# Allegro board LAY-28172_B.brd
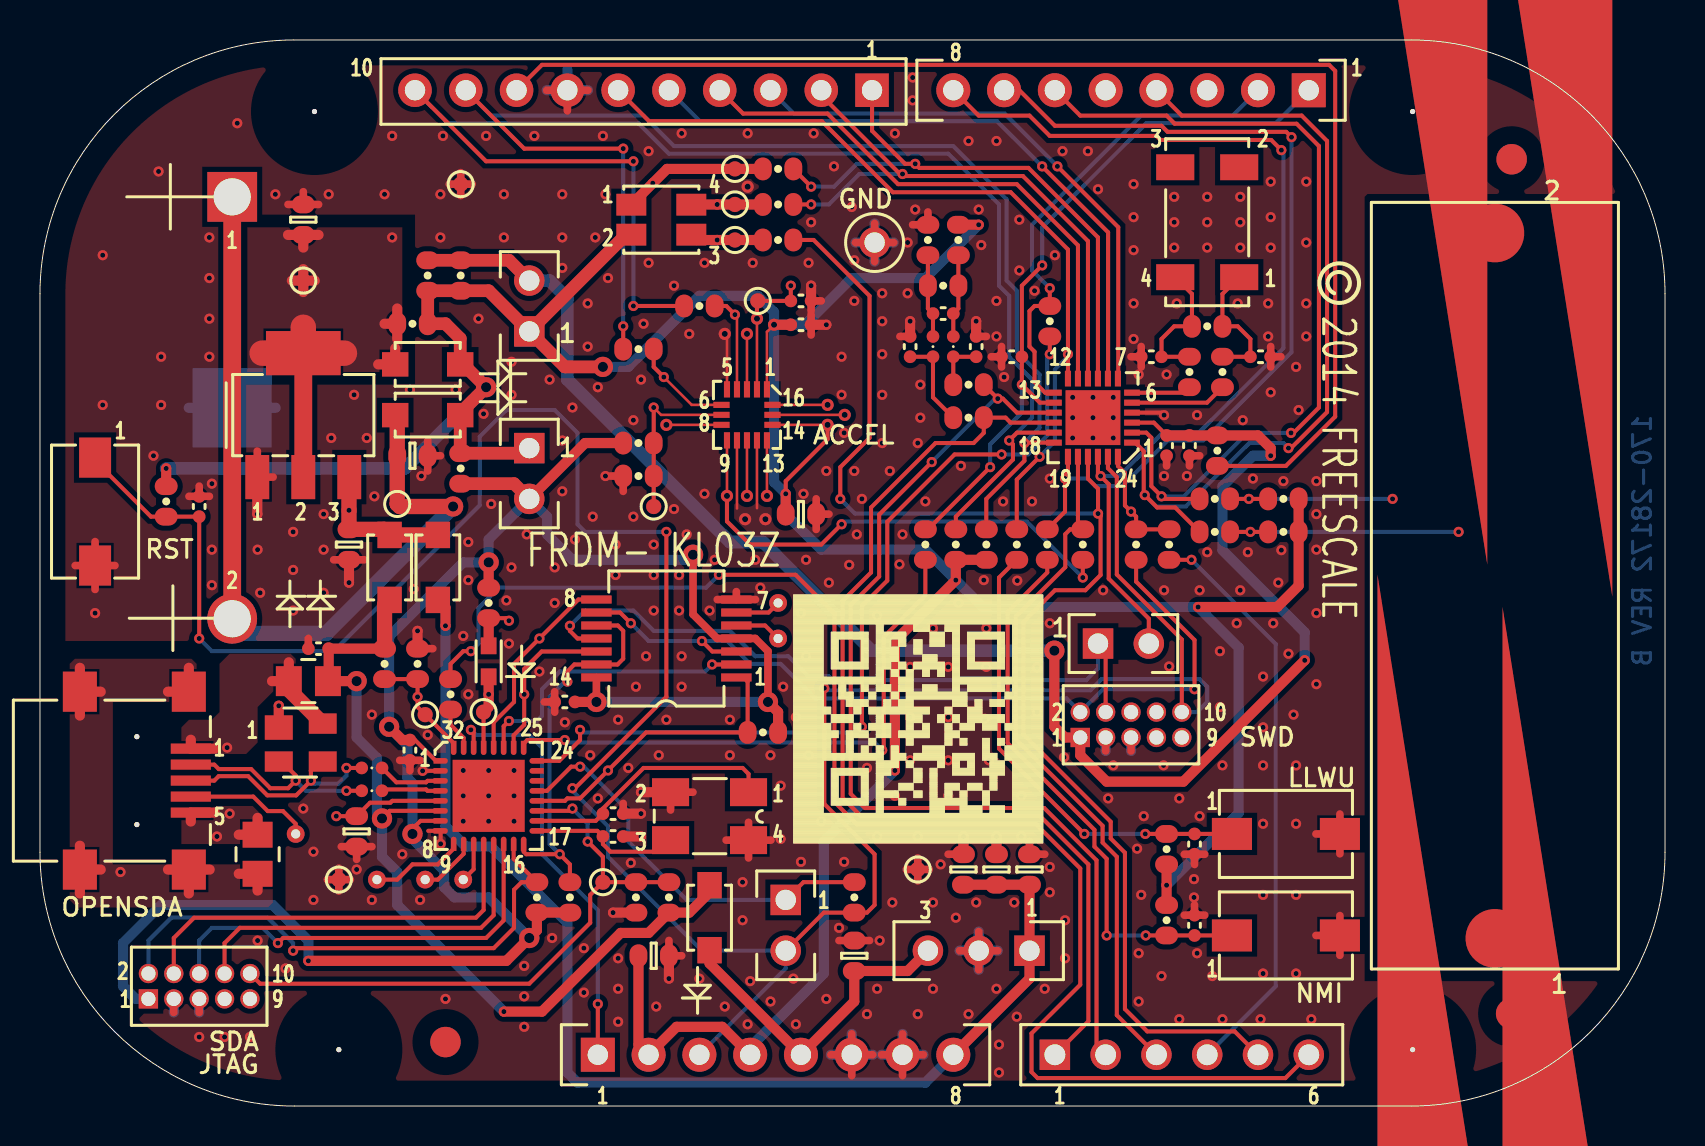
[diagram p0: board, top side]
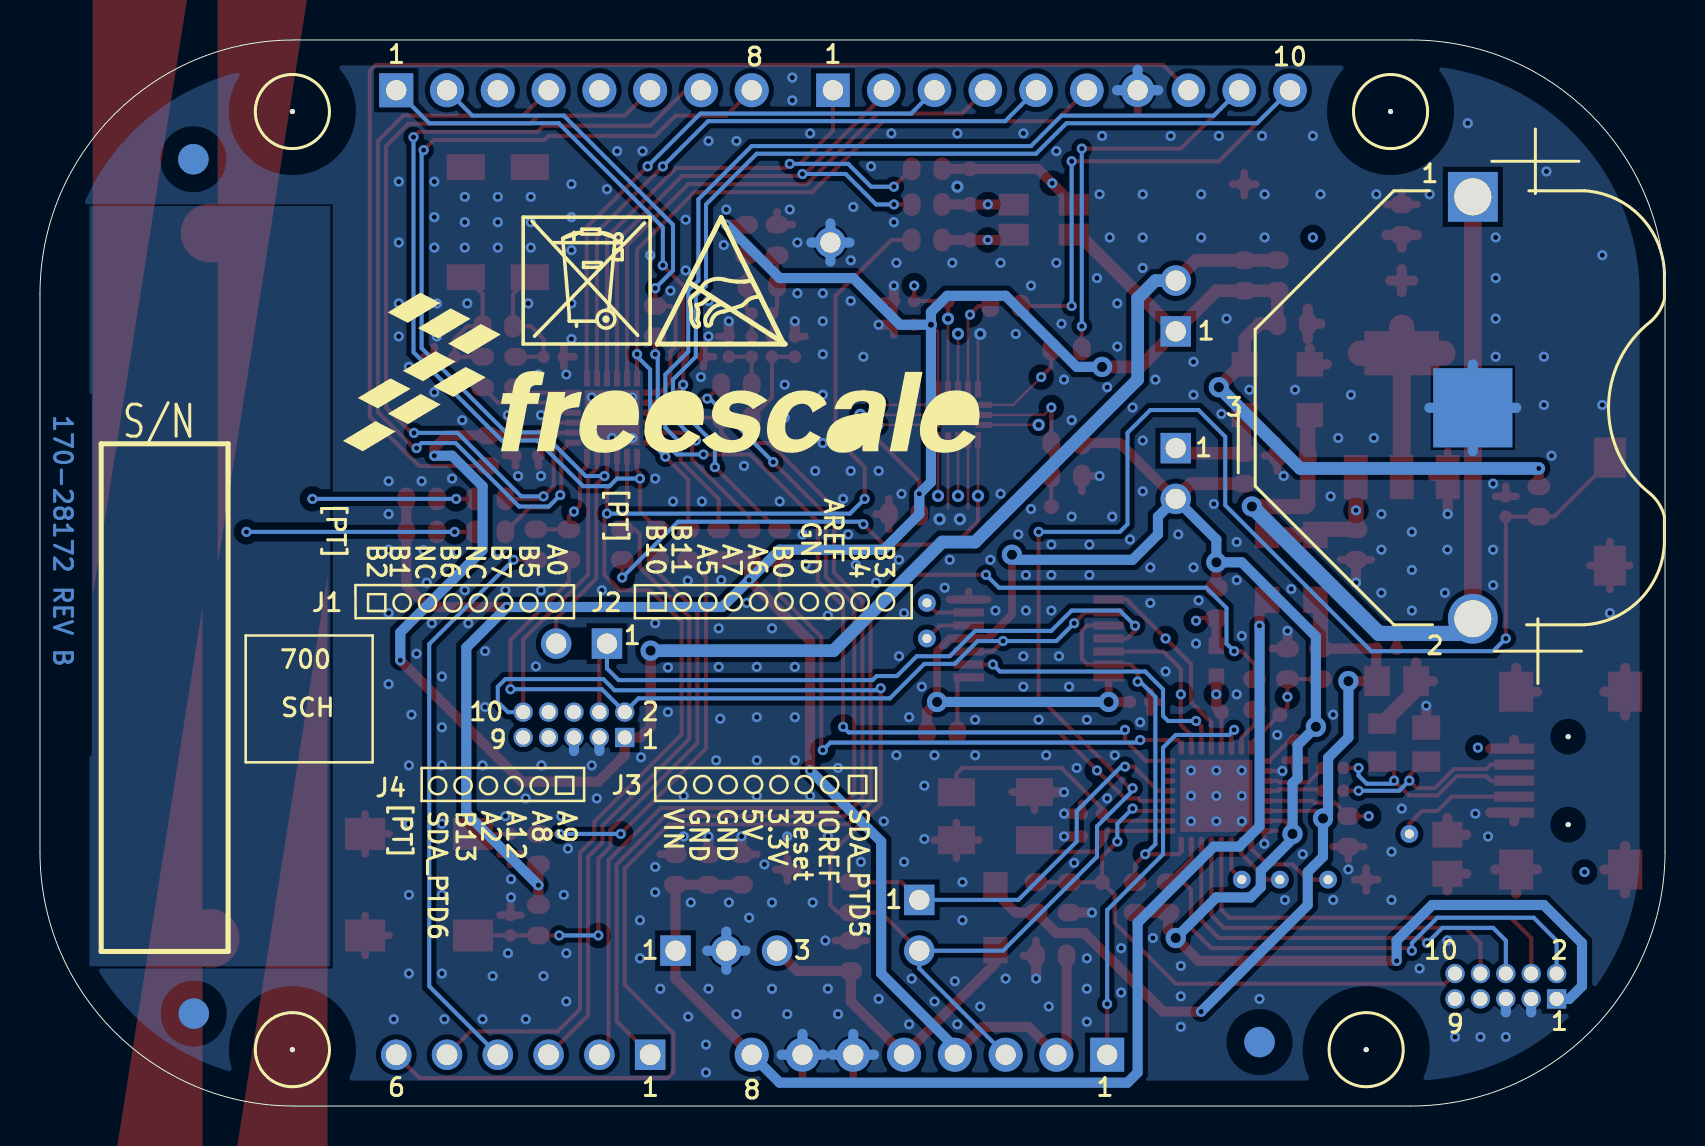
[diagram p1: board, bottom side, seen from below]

Outline 81.28 x 53.34 mm; copper layers: TOP, BOTTOM. Coordinates in mm from the lower left corner of the outline.
Outline path: 0,40.64 0,12.7 arc(3.74,3.72) 12.73,0 68.58,0 arc(77.56,3.72) 81.28,12.7 81.28,40.64 arc(77.56,49.62) 68.58,53.34 12.7,53.34 arc(3.72,49.62) 0,40.64

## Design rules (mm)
net group USB_SI_CONN_D: nets SDA_USB_CONN_DN SDA_USB_CONN_DP
net group USB_SI_D: nets SDA_USB_DN SDA_USB_DP
net group CLOCK: nets EXTAL SDA_EXTAL SDA_XTAL XTAL
net group POWER_SPACE: nets P3V3 P3V3_BATT P5V0_USBSER

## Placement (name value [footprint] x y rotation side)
BT1  3003  [BATT_21X20MM]  9.61 45.49 270 bottom
C1  0.1UF  [CC0402_25]  56.35 33.05 270 top
C2  12PF  [CC0402_25]  61.05 37.49 0 top
C7  12PF  [CC0402_25]  55.59 37.49 180 top
C8  1.0UF  [CC0402_25]  13.93 22.89 180 top
C9  1.0UF  [CC0402_25]  18.5 17.81 270 top
C10  22PF  [CC0402_25]  28.66 14.63 0 top
C11  22PF  [CC0402_25]  28.66 13.49 0 top
C12  2.2UF  [CC0603_OV]  15.84 13.74 270 top
C13  0.1UF  [CC0402_25]  7.96 30 90 top
C14  10uF  [CC0603_OV]  18.63 32.54 0 top
C15  10uF  [CC0603_OV]  15.46 28.09 270 top
C16  10uF  [CC0603_OV]  13.17 44.35 90 top
C17  0.1UF  [CC0402_25]  38.06 39.09 0 top
C18  10uF  [CC0603_OV]  38.06 29.62 0 top
C19  0.1UF  [CC0402_25]  38.06 40.28 0 top
C20  2.2UF  [CC0603_OV]  30.7 7.52 0 top
C22  1.0UF  [CC0402_25]  57.49 33.05 270 top
C26  10uF  [CC0603_OV]  49.49 11.84 90 top
C27  10uF  [CC0603_OV]  47.84 11.84 90 top
C28  10uF  [CC0603_OV]  46.19 11.84 90 top
C29  10uF  [CC0603_OV]  40.73 7.52 90 top
C30  0.1UF  [CC0402_25]  45.17 39.65 180 top
C31  2200PF  [CC0402_25]  43.52 38 90 top
C32  2200PF  [CC0402_25]  46.82 38 90 top
C33  0.1UF  [CC0402_25]  57.75 13.11 270 top
C34  0.1UF  [CC0402_25]  57.75 9.04 90 top
C35  0.1UF  [CC0402_25]  48.6 37.49 180 top
C36  0.1UF  [CC0402_25]  26.25 20.22 180 top
D1  LED GREEN  [LED_0603]  22.44 22.25 270 top
D2  MBR120VLSFT1G  [SOD-123]  17.49 26.95 90 top
D3  MBR120VLSFT1G  [SOD-123]  19.39 37.11 0 top
D4  CLV1A-FKB-CJ1M1F1BB7R4S3  [LED4_3P4X3MM_SMT]  31.08 44.35 90 top
D5  MBR120VLSFT1G  [SOD-123]  33.49 9.42 270 top
D6  TVLS14302AC0  [SOT_143]  13.04 18.19 270 top
D7  MBR120VLSFT1G  [SOD-123]  19.9 26.95 90 top
D8  MBR120VLSFT1G  [SOD-123]  19.39 34.57 0 top
E1  Slider_4  [ELECTRODE_TRI_4_12X38MM]  72.77 26.03 0 top
J1  CON_1X8  [CON_1X8_SKT_2P54_TH]  63.46 50.83 270 top
J2  CON_1X10  [HDR110]  41.62 50.83 270 top
J3  CON_1X8  [CON_1X8_SKT_2P54_TH]  27.9 2.57 90 top
J4  CON_1X6  [CON_SKT1X6_TH]  50.76 2.57 90 top
J5  HDR 1X2 TH  [HDR102]  24.47 32.92 0 top
J6  HDR 1X2 TH  [SH_HDR102_BOTTOM]  52.92 23.14 90 top
J7  HDR 2X5  [HDR_5X2_FTSH_TH_NSP]  52.03 18.44 90 top
J8  HDR 2X5  [HDR_5X2_FTSH_TH_NSP]  5.42 5.36 90 top
J9  USB MINI-B  [CON5_USB_B_UBB]  3.64 16.28 0 top
J10  HDR 1X2 TH  [HDR102]  24.47 38.76 180 top
J11  HDR 1X2 TH  [HDR102]  37.3 10.31 0 top
J22  HDR_1X3  [HDR103]  49.49 7.77 270 top
L3  330 OHM  [IND_0805]  13.42 21.26 0 top
L4  330 OHM  [IND_0805]  10.88 12.6 90 top
NOREF  -  []  12.7 53.34 0 top
NOREF#2  -  []  192.91 64.47 0 top
NOREF#3  -  []  52.42 36.4 0 top
NOREF#4  -  []  34.36 33.31 0 top
NOREF#5  -  []  37.68 13.11 0 top
NOREF#6  -  []  52.92 34.19 0 top
NOREF#7  -  []  34.36 33.31 0 top
NOREF#8  -  []  54.24 36.02 0 top
NOREF#9  -  []  -16.59 -36.7 0 top
NOREF#10  -  []  36.86 36.08 90 top
NOREF#11  -  []  81.28 12.7 90 top
NOREF#12  -  []  34.36 33.31 90 top
NOREF#13  -  []  51.42 36.4 0 top
NOREF#14  -  []  34.09 35.08 90 top
NOREF#15  -  []  33.86 36.08 0 top
NOREF#16  -  []  53.79 37.71 0 top
NOREF#17  -  []  12.88 1.39 0 top
NOREF#18  -  []  39.08 50.83 0 top
NOREF#19  -  []  65.11 41.05 270 top
NOREF#20  -  []  34.36 33.31 0 top
NOREF#21  -  []  13.74 2.72 0 top
NOREF#22  -  []  -381.97 185.27 0 top
NOREF#23  -  [unnamed#2]  20.28 3.2 0 top
NOREF#24  -  []  36.85 39.08 0 top
NOREF#25  -  []  50.59 32.37 90 top
NOREF#26  -  [unnamed#2]  73.61 47.37 0 top
NOREF#27  -  []  34.09 34.58 90 top
NOREF#28  -  []  52.92 34.19 90 top
NOREF#29  -  []  -32.92 -145.92 0 top
NOREF#30  -  []  70.32 0.01 90 top
NOREF#31  -  []  13.74 2.72 0 top
NOREF#32  -  []  54.62 34.19 90 top
NOREF#33  -  []  46.82 49.68 0 top
NOREF#34  -  []  0 41.47 0 top
NOREF#35  -  []  78.12 49.02 0 top
NOREF#36  -  []  54.72 32.37 0 top
NOREF#37  -  []  54.74 32.37 0 top
NOREF#38  -  [unnamed#2]  73.58 4.62 0 top
NOREF#39  -  []  34.09 34.08 0 top
NOREF#40  -  []  54.62 33.19 90 top
NOREF#41  -  []  -408 -339.88 0 top
NOREF#42  -  []  91.82 39.52 180 bottom
NOREF#43  -  []  54.66 12.88 180 bottom
NOREF#44  -  []  82.4 5.51 270 bottom
NOREF#45  -  [unnamed#2]  68.66 2.82 180 bottom
NOREF#46  -  [unnamed#2]  68.66 49.76 180 bottom
NOREF#47  -  [unnamed#2]  73.59 4.63 180 bottom
NOREF#48  -  []  50.38 38.13 180 bottom
NOREF#49  -  []  46.82 49.68 0 bottom
NOREF#50  -  [unnamed#2]  14.95 2.82 180 bottom
NOREF#51  -  []  54.61 5.51 180 bottom
NOREF#52  -  [unnamed#2]  20.28 3.2 180 bottom
NOREF#53  -  []  57.11 38.13 180 bottom
NOREF#54  -  [unnamed#2]  13.73 49.76 180 bottom
NOREF#55  -  [unnamed#2]  73.61 47.37 180 bottom
NOREF#56  -  []  66.13 33.17 180 bottom
R1  0  [RC0603_OV]  59.14 36.73 90 top
R2  10M  [RC0603_OV]  58.38 39.01 180 top
R3  0  [RC0603_OV]  57.49 36.73 90 top
R4  10K  [RC0603_OV]  26.5 10.44 90 top
R5  33  [RC0402_25]  16.6 15.77 0 top
R6  33  [RC0402_25]  16.6 16.92 0 top
R7  10K  [RC0603_OV]  36.16 18.69 0 top
R8  4.7K  [RC0603_OV]  31.46 10.44 90 top
R9  10K  [RC0603_OV]  29.81 10.44 270 top
R10  220  [RC0603_OV]  22.44 25.17 270 top
R11  0  [RC0603_OV]  20.54 20.6 90 top
R12  4.7K  [RC0603_OV]  17.23 22.12 270 top
R13  10K  [RC0603_OV]  6.31 30.25 270 top
R14  10K  [RC0603_OV]  18.88 22.12 90 top
R15  10K  [RC0603_OV]  24.85 10.44 90 top
R16  1K  [RC0603_OV]  50.51 39.27 90 top
R17  1K  [RC0603_OV]  44.28 28.09 90 top
R18  220  [RC0603_OV]  36.92 46.89 180 top
R19  220  [RC0603_OV]  36.92 45.11 0 top
R20  220  [RC0603_OV]  36.92 43.33 0 top
R21  4.7K  [RC0603_OV]  45.81 28.09 90 top
R22  4.7K  [RC0603_OV]  47.33 28.09 90 top
R23  10K  [RC0603_OV]  29.93 33.17 0 top
R24  10K  [RC0603_OV]  29.93 31.52 180 top
R25  0  [RC0603_OV]  58.89 32.79 270 top
R26  0  [RC0603_OV]  52.16 28.09 270 top
R27  0  [RC0603_OV]  19.39 41.55 90 top
R28  0  [RC0603_OV]  21.04 31.9 270 top
R29  510K  [RC0603_OV]  62.19 30.38 180 top
R30  510K  [RC0603_OV]  62.19 28.73 180 top
R31  0  [RC0603_OV]  40.73 10.44 270 top
R32  10  [RC0603_OV]  21.04 41.55 90 top
R33  0  [RC0603_OV]  54.83 28.09 270 top
R34  0  [RC0603_OV]  46.44 36.09 180 top
R35  0  [RC0603_OV]  46.44 34.44 180 top
R36  0  [RC0603_OV]  50.38 28.09 270 top
R37  0  [RC0603_OV]  48.86 28.09 270 top
R38  4.99K  [RC0603_OV]  45.94 43.33 270 top
R39  4.99K  [RC0603_OV]  44.41 43.33 90 top
R40  100  [RC0402_25]  44.67 38 90 top
R41  100  [RC0402_25]  45.68 38 90 top
R44  0  [RC0603_OV]  58.76 28.73 0 top
R45  0  [RC0603_OV]  58.76 30.38 0 top
R48  0  [RC0603_OV]  32.98 40.03 0 top
R49  0  [RC0603_OV]  29.93 37.87 0 top
R52  0  [RC0603_OV]  56.48 28.09 270 top
R53  0  [RC0603_OV]  18.63 39.14 0 top
R54  10K  [RC0603_OV]  56.35 12.85 90 top
R55  10K  [RC0603_OV]  56.35 9.3 270 top
RT1  10K  [RC0603_OV]  45.17 41.05 180 top
SW1  EVQ-PE105K  [SW2_SPST_3P5X6P0_5P0]  2.76 29.74 180 top
SW2  EVQ-PE105K  [SW2_SPST_3P5X6P0_5P0]  62.32 13.61 270 top
SW3  EVQ-PE105K  [SW2_SPST_3P5X6P0_5P0]  62.32 8.53 270 top
TP1  -  [TP_PTH]  21.17 11.33 0 top
TP2  -  [TP_PTH]  12.79 13.61 0 top
TP3  -  [TP_PTH]  19.27 11.33 0 top
TP4  -  [TP_PTH]  16.85 11.33 0 top
TP5  -  [TPAD_030]  28.16 11.2 0 top
TP6  -  [TPAD_030]  22.19 19.71 0 top
TP7  -  [TPAD_030]  19.27 19.58 0 top
TP11  -  [TP_PTH]  36.92 23.39 270 top
TP13  -  [TP_PTH]  36.92 25.17 270 top
TP15  -  [TPAD_030]  17.87 30.12 0 top
TP16  -  [TPAD_030]  13.17 41.3 0 top
TP17  -  [TPAD_030]  34.76 46.89 270 top
TP18  -  [TPAD_030]  34.76 45.11 270 top
TP19  -  [TPAD_030]  34.76 43.33 270 top
TP20  TEST POINT WHITE  [TEST_LOOP]  41.74 43.21 0 top
TP21  -  [TPAD_030]  14.95 11.33 0 top
TP22  -  [TPAD_030]  21.04 46.13 0 top
TP23  -  [TPAD_030]  43.9 11.84 0 top
TP24  -  [TPAD_030]  35.9 40.28 270 top
TP25  -  [TPAD_030]  30.7 30 270 top
U1  PKL03Z16VFK4  [QFN24_0P5_4X4MM]  52.67 34.44 90 top
U2  PK20DX128VFM5  [QFN32_S142EP]  22.44 15.52 0 top
U4  74LVC125ADB  [SSOP14]  31.33 23.39 180 top
U6  NCP1117ST33T3G  [SOT223]  13.17 34.57 0 top
U7  MMA8451Q  [QFN5X3_0P5_3X3]  35.36 34.58 270 top
Y1  32.768KHZ  [XTLOSC4_8X4MM]  58.38 44.22 90 top
Y2  8MHZ  [XTLOSC4_5X3MM_SM]  33.49 14.5 180 top

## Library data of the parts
BT1 = BATTERY_SKT_3V
C1 C2 C7-C20 C22 C26-C36 = CAP_NP
D1 = LED
D2 D3 D5 D7 D8 = DIODE_SCHTKY
D4 = CLV1A_LED_4P
D6 = DIODE_TVS_SOT143
E1 = ELECTRODE_TRI_2
J1 J3 = CONN_HDR_8X1
J2 = RCPT 1X10
J4 = CONN_HDR_6X1
J5 J6 J10 J11 = CONN_HDR_2X1
J7 J8 = CONN_HDR_5X2
J9 = USB_MINI_B_SKT
J22 = CONN_HDR_3X1
L3 L4 = BEAD
R1-R41 R44 R45 R48 R49 R52-R55 = RES
RT1 = THERMISTOR
SW1-SW3 = SW2P
TP1-TP7 TP11 TP13 TP15-TP25 = TESTLOOP
U1 = PKL03Z32_QFN_25P
U2 = PK20DX128V_QFN_32P
U4 = 74-125_14P
U6 = LD1117AS18
U7 = MMA8451Q_16P_A
Y1 = CRYSTAL1-4_SM
Y2 = CRYSTAL_JXS63

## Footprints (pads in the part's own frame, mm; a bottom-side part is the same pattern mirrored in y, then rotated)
BATT_21X20MM
  rect 2.489x2.489 hole 1.854: 1(0,0)
  round 2.489 hole 1.854: 2(21.11,0)
  rect 3.962x3.962 smd: 3(10.555,0)
CC0402_25
  round 0.635 smd: 1(-0.508,0) 2(0.508,0)
CC0603_OV
  oval 0.889x1.143 smd: 1(-0.762,0) 2(0.762,0)
CON5_USB_B_UBB
  round 0.254 hole 1.016 unplated: (1.2,2.2) (1.2,-2.2)
  rect 2.007x0.508 smd: 1(3.9,1.6) 2(3.9,0.8) 3(3.9,0) 4(3.9,-0.8) 5(3.9,-1.6)
  rect 1.702x2.007 smd: S1(3.8,4.45) S2(3.8,-4.45) S3(-1.65,4.45) S4(-1.65,-4.45)
CON_1X8_SKT_2P54_TH
  rect 1.702x1.702 hole 1.016: 1(0,0)
  round 1.702 hole 1.016: 2(0,-2.54) 3(0,-5.08) 4(0,-7.62) 5(0,-10.16) 6(0,-12.7) 7(0,-15.24) 8(0,-17.78)
CON_SKT1X6_TH
  rect 1.524x1.524 hole 1.041: 1(0,0)
  round 1.524 hole 1.041: 2(0,-2.54) 3(0,-5.08) 4(0,-7.62) 5(0,-10.16) 6(0,-12.7)
ELECTRODE_TRI_4_12X38MM
  custom 2.936x2.936 smd: 1(0,-17.645) 2(0,17.645)
HDR102
  rect 1.524x1.524 hole 1.016: 1(0,0)
  round 1.524 hole 1.016: 2(0,-2.54)
HDR103
  rect 1.524x1.524 hole 1.016: 1(0,0)
  round 1.524 hole 1.016: 2(0,-2.54) 3(0,-5.08)
HDR110
  rect 1.676x1.676 hole 1.016: 1(0,0)
  round 1.676 hole 1.016: 2(0,-2.54) 3(0,-5.08) 4(0,-7.62) 5(0,-10.16) 6(0,-12.7) 7(0,-15.24) 8(0,-17.78) 9(0,-20.32) 10(0,-22.86)
HDR_5X2_FTSH_TH_NSP
  rect 0.965x0.965 hole 0.711: 1(0,0)
  round 0.965 hole 0.711: 2(1.27,0) 3(0,-1.27) 4(1.27,-1.27) 5(0,-2.54) 6(1.27,-2.54) 7(0,-3.81) 8(1.27,-3.81) 9(0,-5.08) 10(1.27,-5.08)
IND_0805
  rect 1.295x1.499 smd: 1(-0.978,0) 2(0.978,0)
LED4_3P4X3MM_SMT
  rect 1.092x1.499 smd: 1(0.75,1.5) 2(-0.75,1.5) 3(-0.75,-1.5) 4(0.75,-1.5)
LED_0603
  rect 0.838x0.787 smd: A(-0.775,0) C(0.775,0)
QFN5X3_0P5_3X3
  rect 0.813x0.305 smd: 1(-1.275,1) 2(-1.275,0.5) 3(-1.275,0) 4(-1.275,-0.5) 5(-1.275,-1) 9(1.275,-1) 10(1.275,-0.5) 11(1.275,0) 12(1.275,0.5) 13(1.275,1)
  rect 0.305x0.813 smd: 6(-0.5,-1.275) 7(0,-1.275) 8(0.5,-1.275) 14(0.5,1.275) 15(0,1.275) 16(-0.5,1.275)
QFN24_0P5_4X4MM
  rect 0.305x0.787 smd: 1(-1.25,-1.953) 2(-0.75,-1.953) 3(-0.25,-1.953) 4(0.25,-1.953) 5(0.75,-1.953) 6(1.25,-1.953) 13(1.25,1.953) 14(0.75,1.953) 15(0.25,1.953) 16(-0.25,1.953) 17(-0.75,1.953) 18(-1.25,1.953)
  rect 0.787x0.305 smd: 7(1.953,-1.25) 8(1.953,-0.75) 9(1.953,-0.25) 10(1.953,0.25) 11(1.953,0.75) 12(1.953,1.25) 19(-1.953,1.25) 20(-1.953,0.75) 21(-1.953,0.25) 22(-1.953,-0.25) 23(-1.953,-0.75) 24(-1.953,-1.25)
  rect 2.743x2.743 smd: 25(0,0)
QFN32_S142EP
  custom 0.07x0.07 smd: 1(-2.4,1.751) 2(-2.4,1.251) 3(-2.4,0.751) 4(-2.4,0.25) 5(-2.4,-0.25) 6(-2.4,-0.751) 7(-2.4,-1.251) 8(-2.4,-1.751) 9(-1.751,-2.4) 10(-1.251,-2.4) 11(-0.751,-2.4) 12(-0.25,-2.4) 13(0.25,-2.4) 14(0.751,-2.4) 15(1.251,-2.4) 16(1.751,-2.4) 17(2.4,-1.751) 18(2.4,-1.251) 19(2.4,-0.751) 20(2.4,-0.25) 21(2.4,0.25) 22(2.4,0.751) 23(2.4,1.251) 24(2.4,1.751) 25(1.751,2.4) 26(1.251,2.4) 27(0.751,2.4) 28(0.25,2.4) 29(-0.25,2.4) 30(-0.751,2.4) 31(-1.251,2.4) 32(-1.751,2.4)
  rect 3.607x3.607 smd: 33(0,0)
RC0402_25
  round 0.635 smd: 1(-0.508,0) 2(0.508,0)
RC0603_OV
  oval 0.889x1.143 smd: 1(-0.762,0) 2(0.762,0)
SH_HDR102_BOTTOM
  rect 1.524x1.524 hole 1.016: 1(0,0)
  round 1.524 hole 1.016: 2(0,-2.54)
SOD-123
  rect 1.321x1.219 smd: A(-1.626,0) C(1.626,0)
SOT223
  rect 1.194x2.21 smd: 1(-2.3,-3.1) 2(0,-3.1) 3(2.3,-3.1)
  rect 3.734x2.21 smd: 4(0,3.1)
SOT_143
  rect 1.219x1.397 smd: 1(-0.75,-1.1)
  rect 1.016x1.397 smd: 2(0.95,-1.1) 3(0.95,1.1) 4(-0.95,1.1)
SSOP14
  rect 1.524x0.406 smd: 1(-3.5,1.95) 2(-3.5,1.3) 3(-3.5,0.65) 4(-3.5,0) 5(-3.5,-0.65) 6(-3.5,-1.3) 7(-3.5,-1.95) 8(3.5,-1.95) 9(3.5,-1.3) 10(3.5,-0.65) 11(3.5,0) 12(3.5,0.65) 13(3.5,1.3) 14(3.5,1.95)
SW2_SPST_3P5X6P0_5P0
  rect 1.6x2.007 smd: 1(0,-2.7) 2(0,2.7)
TEST_LOOP
  round 1.524 hole 1.016: 1(0,0)
TP_PTH
  round 0.889 hole 0.457: 1(0,0)
TPAD_030
  round 0.762 smd: 1(0,0)
unnamed#2
  round 1.524 smd: (0,0)
XTLOSC4_5X3MM_SM
  rect 1.854x1.397 smd: 1(-1.95,-1.2) 2(1.95,-1.2) 3(1.95,1.2) 4(-1.95,1.2)
XTLOSC4_8X4MM
  rect 1.295x1.905 smd: 1(-2.75,-1.6) 2(2.75,-1.6) 3(2.75,1.6) 4(-2.75,1.6)

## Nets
GND: BT1.3(NEG) C1.2 C2.2 C7.2 C8.2 C9.2 C10.2 C11.2 C12.2 C13.2 C14.2 C15.2 C16.2 C17.2 C18.2 C19.2 C20.2 C22.2 C26.2 C27.2 C28.2 C29.2 C31.2 C32.2 C33.2 C34.2 C35.2 C36.2 D6.1(GND) J2.7 J3.6 J3.7 J7.3(A2) J7.5(A3) J8.3(A2) J8.5(A3) J9.5(GND1) J22.2 L4.2 R9.2 R14.2 R24.2 R39.2 SW1.2(NO) SW2.2(NO) SW3.2(NO) TP20.1(PIN1) TP21.1(PIN1) TP22.1(PIN1) TP23.1(PIN1) U1.4(VREFL/VSS) U1.25(EXPAD) U2.2(VSS1) U2.8(VSSA) U2.33(EPAD) U4.7(GND) U6.1(GND) U7.5(GND1) U7.10(GND2) U7.12(GND3) Y2.2(GND1) Y2.4(GND2)
P3V3: C17.1 C18.1 C20.1 D3.C D4.2(COMMON_A) D8.C J3.2 J3.4 J5.1 J10.1 R13.1 R21.1 R22.1 R27.1 R28.1 R29.1 R30.1 R32.1 R38.1 R53.2 R54.1 R55.1 U7.1(VDDIO) U7.14(VDD)
P3V3_BATT: BT1.1(POS1) BT1.2(POS2) C14.1 D8.A TP15.1(PIN1)
P3V3_MCU: C1.1 C22.1 J7.1(A1) J10.2 R25.1 R27.2 R32.2 U1.3(VDD/VREFH)
P3V3_USBSER: C9.1 C36.1 J5.2 J8.1(A1) R4.1 R7.2 R10.1 R15.1 R23.1 R28.2 U2.1(VDD1) U2.7(VDDA) U4.4(O\E\2\) U4.14(VCC)
P3V3_VREG: C16.1 D3.A R53.1 TP16.1(PIN1) U6.2(VOUT) U6.4(TAB)
P5V0-9V0_VIN: C26.1 C27.1 C28.1 D7.A J3.8 J22.1
P5V0_SDA_USB_CONN_VBUS: D6.4(VDD) J9.1(VBUS) L3.1
P5V0_USBSER: C8.1 D2.A D5.A L3.2 R8.1 R12.1 U2.6(VREGIN)
P5V_USB_CONNECTORS: C29.1 D5.C J3.5 J22.3
A5: J4.6 R11.2
ACCEL_INT: R26.2 U7.9(INT2)
ACCEL_SCL: R48.2 U7.4(SCL)
ACCEL_SDA: R49.2 U7.6(SDA)
ADC0_SE0/CMP0_IN0/PTA12/IRQ_13/: J4.3 R26.1 U1.20(PTA12/IRQ_13/ADC0_SE0/CMP0_IN0/)
ADC0_SE1/CMP0_IN1/PTB5/IRQ_12/T: J1.7 R36.1 U1.19(PTB5/IRQ_12/ADC0_SE1/CMP0_IN1/T)
ADC0_SE2/PTA9/I2C0_SDA/SPI0_SCK: J4.1 R35.1 U1.16(PTA9/ADC0_SE2/I2C0_SDA/SPI0_SCK)
ADC0_SE3/PTA8/I2C0_SCL/SPI0_MOS: J4.2 R34.1 U1.15(PTA8/ADC0_SE3/I2C0_SCL/SPI0_MOS)
ADC0_SE5/CMP0_IN3/PTB1/IRQ_6/UA: J1.2 R16.2 U1.13(PTB1/IRQ_6/ADC0_SE5/CMP0_IN3/UA)
ADC0_SE6/PTB0/IRQ_5/LLWU_P4/EXT: J2.6 R37.1 U1.12(PTB0/IRQ_5/ADC0_SE6/EXTRG_IN/SP)
ADC0_SE12/CMP0_IN2/PTA0/IRQ_0/L: J1.8 J6.2 U1.22(PTA0/IRQ_0/ADC0_SE12/CMP0_IN2/T)
AREF: J2.8 R25.2
EXTAL: R1.1 U1.5(PTA3/EXTAL0/I2C0_SCL/I2C0_SDA/U)
LEDRGB_BLUE: D4.3(BLUE_C) R20.1 TP19.1(PIN1)
LEDRGB_GREEN: D4.4(GREEN_C) R19.1 TP18.1(PIN1)
LEDRGB_RED: D4.1(RED_C) R18.2 TP17.1(PIN1)
MMA8451_BYP: C19.1 TP24.1(PIN1) U7.2(BYP)
PTA2/CMP0_OUT/SWD_DIO: J4.4 R52.2
PTA5/RTC_CLKIN/TPM0_CH1/SPI0_SS: J2.3 U1.7(PTA5/RTC_CLK_IN/TPM0_CH1/S\P\I\)
PTA6/TPM0_CH0/SPI0_MISO: J2.5 U1.8(PTA6/TPM0_CH0/SPI0_MISO)
PTA7/IRQ_4/SPI0_MISO/SPI0_MOSI: J2.4 U1.11(PTA7/IRQ_4/SPI0_MISO/SPI0_MOSI)
PTB3/IRQ_10/I2C0_SCL/UART0_TX: J2.10 R21.2 R48.1 U1.17(PTB3/IRQ_10/I2C0_SCL/UART0_TX)
PTB4/IRQ_11/I2C0_SDA/UART0_RX: J2.9 R22.2 R49.1 U1.18(PTB4/IRQ_11/I2C0_SDA/UART0_RX)
PTB6/IRQ_2/LPTMR0_ALT3/TPM1_CH1: J1.4 R44.1 U1.1(PTB6/IRQ_2/TPM1_CH1/TPM_CLKIN1/)
PTB7/IRQ_3/TPM1_CH0: J1.6 R45.1 U1.2(PTB7/IRQ_3/TPM1_CH0)
PTB10/TPM0_CH1/SPI0_SS_B: J2.1 R18.1 U1.9(PTB10/TPM0_CH1/S\P\I\0\_\S\S\)
PTB11/TPM0_CH0/SPI0_MISO: J2.2 R19.2 U1.10(PTB11/TPM0_CH0/SPI0_MISO)
PTB13/CLKOUT32K/TPM1_CH1/RTC_CL: J4.5 R20.2 U1.21(PTB13/CLKOUT32K/TPM1_CH1/RTC_CL)
RST_TGTMCU: C13.1 J3.3 J7.10(B5) J11.2 R13.2 R31.2 SW1.1(COMMON) U1.23(PTA1/IRQ_1/TPM_CLKIN0/R\E\S\E\T)
SDA_EXTAL: C11.1 U2.17(EXTAL0/PTA18/FTM0_FLT2/FTM_CLKI) Y2.3
SDA_JTAG_TCLK: J8.4(B2) U2.12(JTAG_TCLK/SWD_CLK/EZP_CLK/TSI0_)
SDA_JTAG_TDI: J8.8(B4) U2.13(JTAG_TDI/EZP_DI/TSI0_CH2/PTA1/U)
SDA_JTAG_TDO: J8.6(B3) U2.14(JTAG_TDO/TRACE_SWO/EZP_DO/TSI0_)
SDA_JTAG_TMS: J8.2(B1) R15.2 U2.15(JTAG_TMS/SWD_DIO/TSI0_CH4/PTA3/)
SDA_LED: D1.C(CATHODE) TP6.1(PIN1) U2.29(PTD4/SPI0_PCS1/U\A\R\T\0\_\R\T\)
SDA_LED_R: D1.A(ANODE) R10.2
SDA_PTD5: J3.1 U2.30(ADC0_SE6B/PTD5/SPI0_PCS2/U\A\R\)
SDA_PTD6: R11.1 U2.31(ADC0_SE7B/PTD6/SPI0_PCS3/UART0_)
SDA_RST: J8.10(B5) R8.2 R9.1 TP5.1(PIN1) U2.19(R\E\S\E\T\)
SDA_RST_TGTMCU: J11.1 R31.1 U2.21(ADC0_SE9/TSI0_CH6/PTB1/I2C0_SDA)
SDA_SPI0_SCK: U2.26(PTC5/SPI0_SCK/LPTMR0_ALT2/I2S0_) U4.12(4A)
SDA_SPI0_SIN: U2.28(CMP0_IN1/PTC7/SPI0_SIN/USB_SOF_) U4.8(3Y)
SDA_SPI0_SOUT: U2.27(CMP0_IN0/PTC6/SPI0_SOUT/PDB0_EX) U4.2(1A)
SDA_SWD_EN: R4.2 U2.16(N\M\I\/E\Z\P\_\C\S\/TSI0_CH5/PT) U4.10(O\E\3\) U4.13(O\E\4\)
SDA_SWD_OE_B: R7.1 U2.20(ADC0_SE8/TSI0_CH0/PTB0/I2C0_SCL) U4.1(O\E\1\)
SDA_USB_CONN_DN: D6.2(I/O1) J9.2(D-) R5.1
SDA_USB_CONN_DP: D6.3(I/O2) J9.3(D+) R6.1
SDA_USB_DN: R5.2 U2.4(USB0_DM)
SDA_USB_DP: R6.2 U2.3(USB0_DP)
SDA_USB_P5V_SENSE: R12.2 R14.1 TP7.1(PIN1) U2.32(PTD7/CMT_IRO/UART0_TX/FTM0_CH7/)
SDA_USB_VOUT33: C12.1 U2.5(VOUT33)
SDA_USBSHIELD: J9.S1(SHLD1) J9.S2(SHLD2) J9.S3(SHLD3) J9.S4(SHLD4) L4.1
SDA_XTAL: C10.1 U2.18(XTAL0/PTA19/FTM1_FLT0/FTM_CLKIN) Y2.1
SW_LLWU: C33.1 R37.2 R54.2 SW2.1(COMMON)
SW_NMI_B: C34.1 R36.2 R55.2 SW3.1(COMMON)
SWD_CLK_TGTMCU: J6.1 J7.4(B2) U4.11(4Y)
SWD_DIO_TGTMCU: J7.2(B1) R33.2 U4.3(1Y) U4.9(3A)
TC_74125_SPARE_I_TP: TP11.1(PIN1) U4.5(2A)
TC_74125_SPARE_O_TP: TP13.1(PIN1) U4.6(2Y)
TC_EXTAL_TP: TP3.1(PIN1) U2.10(EXTAL32)
TC_SDA_USB_ID_TP: J9.4(ID) TP2.1(PIN1)
TC_VBAT_TP: TP1.1(PIN1) U2.11(VBAT)
TC_XTAL_TP: TP4.1(PIN1) U2.9(XTAL32)
THER_A: C32.1 R34.2 R41.1
THER_B: C31.1 R35.2 R40.1
THER_N: C30.2 R39.1 R40.2 RT1.2
THER_P: C30.1 R38.2 R41.2 RT1.1
TOUCH_A: E1.1 R29.2 R45.2
TOUCH_B: E1.2 R30.2 R44.2
UART0_RX_TGTMCU: R17.1 U2.25(PTC4/SPI0_PCS0/UART1_TX/FTM0_CH)
UART0_TX_TGTMCU: R16.1 U2.24(CMP1_IN1/PTC3/SPI0_PCS1/UART1_R)
VREF_CAP/CMP_IN5/PTB2/IRQ_7/UAR: C35.1 J1.1 R17.2 U1.14(PTB2/IRQ_7/VREF_CAP/CMP_IN5/UAR)
XTAL: R3.1 U1.6(PTA4/XTAL0/I2C0_SDA/I2C0_SCL/UA)
N20057318: C15.1 D2.C D7.C U6.3(VIN)
N20181399: R23.2 R24.1 TP25.1(PIN1) U7.7(SA0)
N51885583: C2.1 R1.2 R2.1 Y1.1
N51886520: R33.1 R52.1 U1.24(PTA2/CMP0_OUT/SWD_DIO)
N51910298: C7.1 R2.2 R3.2 Y1.4

Pads without a net: J1 3 5; J7 6 7 8 9; J8 7 9; U2 22 23; U7 3 8 11 13 15 16; Y1 2 3

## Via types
v1: diameter 0.508, hole 0.254, TOP to BOTTOM, 490 vias
v2: diameter 0.61, hole 0.305, TOP to BOTTOM, 14 vias
v3: diameter 1.016, hole 0.508, TOP to BOTTOM, 13 vias

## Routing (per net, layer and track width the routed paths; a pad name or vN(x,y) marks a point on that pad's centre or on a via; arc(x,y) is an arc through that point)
GND: length 147.3
  TOP w0.127: 34.86,29.9 U7.10 ; 35.86,29.91 U7.12 ; v2(34.25,38.63) 34.36,38.52 U7.5
  TOP w0.203: U1.4 56.1,34.69 v1(56.22,34.57) ; v1(20.04,13.12) U2.8 19.42,13.77 ; U2.2 v1(19.14,16.77)
  TOP w0.381: 12.4,45.11 C16.2 ; C16.2 13.93,45.11 ; C16.2 13.17,45.75 ; 48.09,36.98 C35.2 ; C35.2 47.58,37.49 ; C35.2 48.09,38 ; C13.2 7.96,31.02 ; C13.2 7.45,30.51 ; C13.2 8.47,30.51 ; SW3.2 65.02,9.53 ; SW3.2 65.02,7.54 ; SW3.2 63.82,8.53 ; 1.76,27.04 SW1.2 ; SW1.2 3.75,27.04 ; SW1.2 2.76,28.24 ; SW1.2 2.76,25.85 ; C2.2 61.56,38 ; C2.2 61.56,36.98 ; C2.2 62.07,37.49 ; 20.47,46.13 TP22.1 ; TP22.1 21.04,46.7 ; TP22.1 21.04,45.55 ; TP22.1 21.62,46.13 ; C8.2 13.42,23.4 ; 26.38,49.79 J2.7 ; J2.7 25.35,50.83 ; J2.7 27.41,50.83 ; C10.2 29.17,15.14 ; 7.96,4.68 J8.5 ; 10.87,32.77 U6.1 11.66,31.47 ; 50.26,12.6 C26.2 49.49,13.24 ; 43.14,1.52 J3.7 ; J3.7 44.19,2.57 ; J3.7 42.1,2.57 ; J3.7 43.14,3.61 ; 18.5,16.79 C9.2 ; C9.2 17.99,17.3 ; C9.2 19.01,17.3 ; R14.2 19.65,22.89 ; 25.23,20.22 C36.2 ; C36.2 25.74,19.71 ; C36.2 25.74,20.73 ; 57.24,12.6 C33.2 ; C33.2 58.26,12.6 ; C33.2 57.75,12.09 ; C7.2 55.08,38 ; C7.2 54.57,37.49 ; C7.2 55.08,36.98 ; 46.95,6.82 J22.2 ; J22.2 47.91,7.77 ; J22.2 46,7.77 ; J22.2 46.95,8.73 ; 14.37,11.33 TP21.1 ; TP21.1 14.95,10.75 ; TP21.1 15.52,11.33 ; TP21.1 14.95,11.9 ; C34.2 58.26,9.55 ; C34.2 57.24,9.55 ; C34.2 57.75,10.06 ; 33.88,25.34 U4.7 ; U4.7 35.79,25.34 ; U4.7 34.83,25.74 ; TP23.1 44.48,11.84 ; TP23.1 43.9,11.26 ; TP23.1 43.33,11.84 ; TP23.1 43.9,12.41 ; 54.57,17.76 J7.5 ; 57.49,32.03 C22.2 58,32.54 ; 38.57,39.6 C17.2 38.57,38.58 ; Y2.4 36.56,13.3 ; Y2.4 35.44,12.41 ; Y2.4 34.32,13.3 ; Y2.4 35.44,14.2 ; 41.49,8.28 C29.2 39.96,8.28 ; 45.42,12.6 C28.2 ; 14.69,27.33 C15.2 16.22,27.33 ; 15.84,12.34 C12.2 ; C12.2 15.07,12.98 ; C12.2 16.6,12.98 ; 63.82,13.61 SW2.2 ; SW2.2 65.02,14.61 ; SW2.2 65.02,12.62 ; 43.65,44.09 R39.2 44.41,44.73 ; TP20.1 42.7,43.21 ; TP20.1 40.79,43.21 ; TP20.1 41.74,44.16 ; TP20.1 41.74,42.25 ; J3.6 40.6,3.61 ; J3.6 40.6,1.52 ; J3.6 39.56,2.57 ; J3.6 41.65,2.57 ; 39.08,40.28 C19.2 38.57,39.77 ; 43.01,38.51 C31.2 ; 32.66,15.7 Y2.2 31.54,14.81 ; 31.46,8.28 C20.2 32.1,7.52 ; C14.2 19.39,33.3 ; C14.2 20.03,32.54 ; C14.2 19.39,31.77 ; C18.2 39.46,29.62 ; C18.2 38.82,30.38 ; C18.2 38.82,28.85 ; 56.35,32.03 C1.2 ; 28.53,31.52 R24.2 29.17,30.76 ; C32.2 47.34,38.51 ; 53.3,17.76 J7.3 ; 6.69,4.68 J8.3
  TOP w0.508: v1(47.84,13.49) C27.2 ; C11.2 v1(30.06,13.49) ; 8.74,14.68 J9.5 7.54,14.24 ; 9.94,13.58 L4.2 10.88,14.42 ; C32.2 v1(46.82,39.27) ; v1(46.19,13.49) C28.2 ; v1(38.57,41.05) C19.2 ; C10.2 v1(30.06,14.63) ; C20.2 v1(31.46,6.38) ; C31.2 v1(43.52,39.27) ; v1(30.06,15.7) Y2.2 ; R14.2 v1(18.88,23.77) ; C15.2 v1(15.46,26.19) ; D6.1 v1(11.94,20.03) ; C17.2 v1(39.33,39.09) ; R9.2 v1(28.66,9.68) ; U6.1 v1(10.87,29.62)
  BOTTOM w0.508: 39.56,2.57 J3.6 ; J3.6 41.65,2.57 ; J3.6 40.6,3.61 ; 7.44,34.94 BT1.3 ; BT1.3 9.61,32.76 ; BT1.3 11.79,34.94 ; BT1.3 9.61,37.11 ; 7.96,4.68 J8.5 ; TP20.1 41.74,44.16 ; TP20.1 40.79,43.21 ; TP20.1 41.74,42.25 ; TP20.1 42.7,43.21 ; J22.2 46.95,8.73 ; J22.2 47.91,7.77 ; J22.2 46.95,6.82 ; J22.2 46,7.77 ; 6.69,4.68 J8.3 ; J3.7 44.19,2.57 ; J3.7 43.14,3.61 ; J3.7 42.1,2.57 ; J2.7 26.38,51.86 ; J2.7 27.41,50.83 ; J2.7 25.35,50.83 ; 53.3,17.76 J7.3 ; 54.57,17.76 J7.5
  vias: v1(2.76,24.66) v1(3.14,42.57) v1(3.14,35.08) v1(5.68,32.54) v1(5.93,46.76) v1(6.06,37.49) v1(6.06,35.08) v1(7.96,3.45) v1(8.47,43.46) v1(8.47,41.43) v1(8.47,39.4) v1(8.47,37.49) v1(8.6,31.14) v1(8.6,27.84) v1(8.6,26.06) v1(8.85,13.49) v1(9.23,3.45) v1(9.49,14.63) v1(9.87,49.17) v1(10.5,3.45) v1(10.88,27.84) v1(10.88,8.28) v1(11.01,25.68) v1(11.77,45.62) v1(12.28,6.88) v1(12.66,28.73) v1(12.66,26.82) v1(12.66,24.79) v1(13.17,14.88) v1(13.68,12.73) v1(13.68,10.31) v1(14.19,29.62) v1(14.19,27.84) v1(14.19,25.68) v1(14.44,45.62) v1(14.57,33.43) v1(15.71,35.59) v1(15.84,11.84) v1(16.34,33.43) v1(16.6,19.58) v1(16.6,10.31) v1(16.73,30.51) v1(17.23,45.62) v1(17.61,48.54) v1(18.12,12.6) v1(18.5,35.84) v1(18.69,25.87) v1(19.08,31.52) v1(19.01,10.31) v1(19.39,18.57) v1(20.03,45.62) v1(20.03,43.46) v1(20.15,48.54) v1(20.28,5.36) v1(20.79,35.84) v1(21.17,23.52) v1(21.17,16.79) v1(21.17,15.52) v1(21.17,14.25) v1(21.42,28.22) v1(21.42,26.31) v1(21.42,20.6) v1(21.93,39.4) v1(22.19,34.63) v1(22.31,48.54) v1(22.44,16.79) v1(22.44,15.52) v1(22.44,14.25) v1(22.57,30.12) v1(23.2,45.62) v1(23.2,43.46) v1(23.33,25.3) v1(23.46,23.14) v1(23.58,37.24) v1(23.58,35.59) v1(23.58,26.95) v1(23.71,16.79) v1(23.71,15.52) v1(23.71,14.25) v1(24.22,7.01) v1(24.22,5.49) v1(24.22,3.96) v1(24.35,28.6) v1(24.73,48.54) v1(24.98,21.74) v1(25.49,36.35) v1(25.62,8.41) v1(25.74,26.95) v1(25.74,25.17) v1(26.12,45.62) v1(26.12,43.46) v1(26.12,41.94) v1(26.12,33.3) v1(26.12,30.76) v1(26.25,19.2) v1(26.63,34.95) v1(26.76,28.35) v1(27.2,7.9) v1(27.2,5.68) v1(27.39,40.16) v1(27.39,38) v1(27.52,17.55) v1(27.65,29.49) v1(27.77,43.46) v1(27.9,35.97) v1(27.9,15.39) v1(28.16,48.54) v1(28.28,45.62) v1(28.28,31.52) v1(28.41,41.43) v1(28.79,28.09) v1(28.79,26.57) v1(28.92,19.33) v1(28.92,7.39) v1(28.92,5.87) v1(28.92,4.22) v1(29.43,16.92) v1(29.55,12.17) v1(29.68,34.32) v1(29.68,29.49) v1(29.81,20.98) v1(30.06,36.35) v1(30.19,39.14) v1(30.31,22.5) v1(30.44,47.78) v1(30.44,42.19) v1(30.7,28.09) v1(30.7,26.57) v1(30.7,24.79) v1(30.82,4.98) v1(30.95,17.55) v1(31.33,19.33) v1(31.71,41.05) v1(31.71,29.87) v1(31.97,26.57) v1(31.97,24.79) v1(32.09,48.67) v1(32.09,22.5) v1(32.09,20.98) v1(32.35,28.6) v1(32.47,38.63) v1(32.98,6.38) v1(33.24,42.19) v1(33.24,30.63) v1(33.49,24.79) v1(33.74,27.33) v1(34.25,4.98) v1(34.51,19.33) v1(34.51,17.55) v1(35.14,11.2) v1(35.14,9.3) v1(35.39,48.67) v1(35.39,4.09) v1(35.52,6.25) v1(35.65,42.19) v1(35.78,27.33) v1(36.03,25.93) v1(36.54,17.55) v1(36.54,5.23) v1(37.05,16.03) v1(37.05,13.36) v1(37.17,20.98) v1(37.68,6.38) v1(37.81,19.46) v1(37.81,4.09) v1(38.06,24.66) v1(38.06,12.22) v1(38.19,30.63) v1(38.32,27.33) v1(38.32,22.5) v1(38.44,42.19) v1(38.44,17.55) v1(38.57,44.22) v1(38.7,48.67) v1(39.08,14.25) v1(39.33,31.78) v1(39.33,5.36) v1(39.46,26.19) v1(39.71,47.02) v1(39.97,8.92) v1(40.09,37.49) v1(40.09,35.59) v1(40.22,33.68) v1(40.22,12.22) v1(40.47,27.08) v1(40.6,44.98) v1(40.73,42.32) v1(40.73,40.28) v1(40.73,31.78) v1(40.86,28.6) v1(41.11,30.38) v1(41.36,16.92) v1(41.36,4.6) v1(41.87,24.54) v1(41.87,13.49) v1(41.87,5.87) v1(42,8.28) v1(42.13,40.67) v1(42.13,39.27) v1(42.13,37.62) v1(42.13,35.59) v1(42.13,33.17) v1(42.51,31.78) v1(42.63,10.19) v1(42.76,48.67) v1(42.76,15.52) v1(42.99,27.1) v1(43.14,28.6) v1(43.4,43.21) v1(43.4,40.67) v1(43.52,21.97) v1(43.52,19.46) v1(43.52,17.3) v1(43.65,51.46) v1(43.65,50.32) v1(43.78,44.86) v1(43.9,33.17) v1(43.9,13.49) v1(43.9,4.6) v1(44.03,36.09) v1(44.03,34.44) v1(44.28,30.25) v1(44.67,23.9) v1(44.67,10.19) v1(44.67,5.87) v1(45.05,12.09) v1(45.43,21.97) v1(45.43,19.46) v1(45.43,17.3) v1(45.43,15.52) v1(45.81,9.42) v1(45.94,25.17) v1(46.06,32.03) v1(46.44,48.29) v1(46.44,4.6) v1(46.82,10.19) v1(46.95,44.86) v1(47.08,43.08) v1(47.21,26.31) v1(47.26,19.38) v1(47.33,23.9) v1(47.33,21.97) v1(47.46,17.3) v1(47.84,48.29) v1(47.84,40.28) v1(47.84,38.51) v1(47.84,5.87) v1(47.97,3.07) v1(47.97,1.68) v1(48.17,30.25) v1(48.22,36.47) v1(48.73,10.19) v1(48.88,26.29) v1(48.86,4.47) v1(48.98,44.35) v1(48.98,41.81) v1(49.09,15.52) v1(49.09,13.49) v1(49.62,30.25) v1(49.75,40.79) v1(49.87,21.95) v1(49.87,19.71) v1(50.25,5.87) v1(50.51,31.39) v1(50.51,24.16) v1(50.51,11.96) v1(50.51,10.69) v1(50.76,42.57) v1(51.14,47.78) v1(51.22,17.45) v1(51.27,9.3) v1(51.27,7.39) v1(51.65,35.46) v1(51.65,34.44) v1(51.65,33.43) v1(52.41,47.78) v1(52.67,35.46) v1(52.67,34.44) v1(52.67,33.43) v1(52.92,45.87) v1(53.17,25.81) v1(53.43,15.39) v1(53.68,35.46) v1(53.68,34.44) v1(53.68,33.43) v1(53.68,17.04) v1(54.7,46.13) v1(54.7,44.48) v1(54.7,42.82) v1(54.7,40.16) v1(54.7,38.38) v1(54.88,12.88) v1(54.95,36.6) v1(54.95,7.65) v1(54.95,5.23) v1(55.08,10.57) v1(55.21,14.5) v1(56.1,6.5) v1(56.2,17.04) v1(56.22,31.52) v1(56.22,25.81) v1(56.35,36.6) v1(56.48,22) v1(56.73,45.49) v1(56.73,44.22) v1(56.73,42.95) v1(56.86,40.16) v1(56.98,15.39) v1(56.98,4.34) v1(57.37,31.52) v1(57.72,11.35) v1(57.72,10.44) v1(57.87,34.57) v1(57.87,7.65) v1(58,25.81) v1(58,14.5) v1(58.38,45.49) v1(58.38,44.22) v1(58.38,42.95) v1(58.38,27.71) v1(58.64,6.5) v1(59.02,22.76) v1(59.02,19.96) v1(59.14,17.04) v1(59.14,4.34) v1(59.86,24.16) v1(59.91,40.16) v1(60.03,45.49) v1(60.03,44.22) v1(60.03,42.95) v1(60.03,25.81) v1(60.16,34.32) v1(60.41,27.71) v1(60.67,31.39) v1(61.05,4.34) v1(61.18,21.49) v1(61.18,18.95) v1(61.18,17.04) v1(61.18,14.12) v1(61.18,10.57) v1(61.18,6.63) v1(61.43,40.16) v1(61.43,38.51) v1(61.56,46.25) v1(61.56,44.48) v1(61.56,42.95) v1(61.56,35.71) v1(61.68,24.16) v1(61.94,26.19) v1(62.09,27.81) v1(62.19,31.27) v1(62.45,22.63) v1(62.7,19.58) v1(62.83,36.98) v1(62.83,17.04) v1(62.83,14.12) v1(62.83,10.57) v1(62.83,6.63) v1(62.95,34.82) v1(63.33,46.25) v1(63.33,43.21) v1(63.33,40.16) v1(63.33,38.51) v1(63.59,4.34) v1(63.84,31.27) v1(63.84,29.62) v1(63.84,27.84) v1(63.84,24.66) v1(63.84,21.11) v2(35.27,29.36) v2(35.39,46) v2(36.28,29.36)
P3V3: length 189
  TOP w0.127: U7.14 v2(39.39,34.08) ; U7.1 36.36,38.74 v2(36.72,39.09)
  TOP w0.203: v1(37.3,30.63) 37.3,31.27 39.39,33.36 v2(39.39,34.08)
  TOP w0.508: C17.1 v2(36.72,39.09) ; R29.1 R30.1 62.95,26.03 61.89,24.97 v1(57.92,24.97) ; R22.1 R21.1 v1(45.81,26.31) 42.76,23.27 v1(42.76,16.79) ; R38.1 v1(46.95,44.09) ; R55.1 v1(56.35,11.05) 56.35,12.09 ; C20.1 29.93,3.07 J3.2 31.84,3.96 34.12,3.96 J3.4 ; R13.1 v1(6.31,31.9) ; C18.1 v1(37.3,30.63)
  TOP w0.635: D4.2 29.31,43.6 J10.1 ; J10.1 26.25,36.98 v3(28.16,36.98) ; J10.1 22.44,40.79 R32.1 R27.1 R53.2 20.28,39.14 21.02,38.4 D3.C 21.17,37.11 v3(22.31,35.97) 21.02,34.67 D8.C 21.02,32.69 R28.1 24.22,32.66 J5.1
  BOTTOM w0.508: J3.4 35.52,2.95 39.2,6.63 39.2,13.23 v1(42.76,16.79) ; v2(36.72,39.09) 36.72,31.22 v1(37.3,30.63) C18.1 39.08,27.84 44.28,27.84 v1(45.81,26.31) 47.16,24.97 v1(57.92,24.97) 59.96,22.94 59.96,14.66 v1(56.35,11.05) ; v2(36.72,39.09) 36.72,39.73 35.9,40.54 32.98,40.54 29.43,36.98 v3(28.16,36.98) ; v2(36.72,39.09) 38.27,39.09 40.6,41.43 44.28,41.43 v1(46.95,44.09)
  BOTTOM w0.635: v1(6.31,31.9) 18.25,31.9 v3(22.31,35.97)
P3V3_BATT: length 42.4
  TOP w0.762: D8.A 17.87,34.47 C14.1 TP15.1 18,30 v3(20.66,30)
  TOP w0.889: BT1.1 BT1.2
  BOTTOM w0.762: BT1.2 10.35,23.65 14.31,23.65 v3(20.66,30)
P3V3_MCU: length 83.6
  TOP w0.203: C1.1 55.71,34.19 U1.3
  TOP w0.508: v1(61.56,32.54) 61.56,32.92 60.92,33.55 R25.1 C22.1 C1.1 ; v1(63.26,22.3) 57.19,16.23 53.35,16.23 52.03,17.55 J7.1 51.27,18.44 50.74,18.97 v3(50.74,22.78)
  TOP w0.635: J10.2 23.46,42.32 R32.2 R27.2
  BOTTOM w0.508: v1(63.26,22.3) 63.26,23.7 59.14,27.81 59.14,31.01 60.67,32.54 v1(61.56,32.54)
  BOTTOM w0.635: J10.2 25.49,41.3 26.38,40.41 26.38,36.35 34.51,28.22 36.16,28.22 41.59,22.78 v3(50.74,22.78)
P3V3_USBSER: length 108.3
  TOP w0.203: U2.1 19.8,17.27 18.76,18.31 C9.1 ; v3(18.63,13.61) 18.63,13.87 19.03,14.27 U2.7
  TOP w0.381: U4.14 v3(27.83,20.22) ; v3(36.41,20.22) 36.41,22.76 35.78,23.39 U4.4 33.87,23.39 32.66,24.6 v3(32.66,27.58)
  TOP w0.508: R23.1 27.27,33.17 J5.2 ; v3(17.46,18.97) 18.12,18.31 C9.1 ; v1(13.42,7.26) 23.33,7.26 v3(24.47,8.41) 24.85,8.79 R15.1 R4.1 ; R10.1 v3(22.44,27.2) ; v3(36.41,20.22) 36.92,19.71 R7.2 ; C36.1 v3(27.83,20.22)
  TOP w0.635: J5.2 23.71,31.14 R28.2
  BOTTOM w0.508: v3(24.47,8.41) 22.44,10.44 20.73,10.44 20.22,10.95 20.22,11.77 18.63,13.36 v3(18.63,13.61) 18.63,16.15 18.38,16.41 18.38,18.06 v3(17.46,18.97) 17.46,23.49 21.17,27.2 v3(22.44,27.2) 22.44,28.35 J5.2 25.36,29.49 25.36,28.6 26.63,27.33 32.41,27.33 v3(32.66,27.58) ; v1(13.42,7.26) 13.42,8.28 11.65,10.06 6.06,10.06 4.15,8.15 4.15,5.99 4.79,5.36 J8.1 ; v3(36.41,20.22) v3(27.83,20.22)
P3V3_VREG: length 19.9
  TOP w0.508: C16.1 13.93,43.59 ; C16.1 12.41,43.59 ; C16.1 13.17,42.95 ; 13.17,40.73 TP16.1 ; TP16.1 13.74,41.3 ; TP16.1 12.6,41.3 ; TP16.1 13.17,41.87 ; 16.92,37.11 D3.A 17.77,37.91 ; R53.1 17.87,39.9 ; R53.1 17.87,38.38 ; R53.1 17.23,39.14
  TOP w0.889: U6.2 U6.4
  TOP w1.27: U6.4 15.23,37.67 ; U6.4 11.11,37.67 ; U6.4 13.17,38.97
  vias: v1(17.61,43.46)
P5V0-9V0_VIN: length 60.6
  TOP w0.508: 46.19,11.07 49.49,11.07 J22.1 49.49,6.38 J3.8 ; v1(20.28,24.03) 20.28,24.94 D7.A
  BOTTOM w0.508: v1(20.28,24.03) 20.28,14 21.3,12.98 22.57,12.98 26.38,9.17 26.38,1.68 26.89,1.17 44.28,1.17 J3.8
P5V0_SDA_USB_CONN_VBUS: length 6.2
  TOP w0.508: 7.54,18.33 J9.1 8.74,17.88 ; 11.61,21.26 L3.1 12.45,22.2
  TOP w0.762: L3.1 12.45,20.83 D6.4
  vias: v1(9.36,17.93)
P5V0_USBSER: length 44.2
  TOP w0.203: v3(17.11,14.39) 17.49,14.77 U2.6
  TOP w0.508: v3(15.84,21.26) L3.2 14.44,21.3 C8.1 R12.1 ; D5.A 33.49,10.69 32.47,9.68 R8.1 30.44,8.66 29.04,8.66 25.11,4.72 v1(23.2,4.72)
  TOP w0.762: D2.A 17.23,25.07 R12.1
  BOTTOM w0.508: v3(15.84,21.26) 15.84,18.44 16.85,17.42 16.85,14.64 v3(17.11,14.39) 17.11,12.47 17.87,11.71 17.87,10.06 v1(23.2,4.72)
P5V_USB_CONNECTORS: length 16.5
  TOP w0.508: J22.3 43.4,6.76 C29.1 40.73,5.23 J3.5 33.49,7.14 D5.C
A5: length 72.4
  TOP w0.203: v1(33.96,26.58) 37.8,26.58 39.74,24.64 39.74,15.21 40.86,14.1 49.82,14.1 52.03,11.89 52.03,6.07 49.59,3.63 49.59,1.7 49.9,1.4 62.29,1.4 J4.6 ; v1(21.55,22.76) 21.17,22.76 20.54,22.12 R11.2
  BOTTOM w0.203: v1(33.96,26.58) 33.31,25.93 22.95,25.93 21.93,24.92 21.93,23.14 v1(21.55,22.76)
ACCEL_INT: length 24.9
  TOP w0.127: U7.9 v2(34.36,30.53)
  TOP w0.203: v2(34.36,30.53) 34.36,29.25 35.52,28.09 39.08,28.09 v1(40.09,29.11) ; R26.2 v1(52.16,26.44)
  BOTTOM w0.203: v1(40.09,29.11) 40.22,29.24 49.36,29.24 v1(52.16,26.44)
ACCEL_SCL: length 5
  TOP w0.127: v1(34.76,39.6) 34.86,39.5 U7.4
  TOP w0.203: v1(34.76,39.6) 34.33,40.03 R48.2
ACCEL_SDA: length 5.1
  TOP w0.127: v1(31.2,36.47) 32.6,35.08 U7.6
  TOP w0.203: R49.2 30.7,36.98 v1(31.2,36.47)
ADC0_SE0/CMP0_IN0/PTA12/IRQ_13/: length 34.7
  TOP w0.203: U1.20 51.92,29.1 R26.1 51.52,28.85 51.28,28.61 51.28,26.96 48.81,24.49 48.81,18.36 53.15,14.02 53.15,13.18 53.86,12.47 53.86,4.55 J4.3
ADC0_SE1/CMP0_IN1/PTB5/IRQ_12/T: length 44.4
  TOP w0.203: U1.19 51.42,31.8 51.27,31.65 v1(51.27,31.39) 51.27,29.74 R36.1 ; v1(62.6,48.48) 62.33,48.74 56.4,48.74 56.1,49.05 50.76,49.05 48.98,50.83 J1.7
  BOTTOM w0.203: v1(51.27,31.39) 52.41,31.39 52.79,31.01 54.11,31.01 56.4,33.3 58.18,33.3 62.6,37.72 v1(62.6,48.48)
ADC0_SE2/PTA9/I2C0_SDA/SPI0_SCK: length 50.6
  TOP w0.203: U1.16 48.55,34.19 48.3,34.44 R35.1 47.21,33.68 46.7,33.17 44.79,33.17 41.57,29.95 41.57,26.7 40.14,25.27 40.14,15.42 41.06,14.5 50.03,14.5 52.44,12.09 52.44,4.24 J4.1
ADC0_SE3/PTA8/I2C0_SCL/SPI0_MOS: length 50.6
  TOP w0.203: v1(44.6,32.22) 41.97,29.59 41.97,26.49 40.55,25.07 40.55,15.62 41.26,14.91 50.23,14.91 52.84,12.29 52.84,3.02 J4.2 ; U1.15 48.86,34.69 48.16,35.39 v1(47.9,35.39) R34.1
  BOTTOM w0.203: v1(44.6,32.22) 47.78,35.39 v1(47.9,35.39)
ADC0_SE5/CMP0_IN3/PTB1/IRQ_6/UA: length 24.5
  TOP w0.203: v1(50.51,40.92) R16.2 49.75,40.03 49.49,39.78 49.49,38 49.75,37.74 49.75,36.22 50.27,35.69 U1.13
  BOTTOM w0.203: v1(50.51,40.92) 49.62,41.81 49.62,44.09 55.08,49.56 59.65,49.56 J1.2
ADC0_SE6/PTB0/IRQ_5/LLWU_P4/EXT: length 42.1
  TOP w0.203: v1(50,32.49) 48.86,31.34 R37.1 ; J2.6 30.47,49.28 39.1,49.28 42.66,45.72 48.55,45.72 51.42,42.86 v1(51.42,37.62) U1.12
  BOTTOM w0.203: v1(50,32.49) 50.76,33.25 50.76,36.86 51.42,37.51 v1(51.42,37.62)
ADC0_SE12/CMP0_IN2/PTA0/IRQ_0/L: length 49.8
  TOP w0.203: v1(62.09,47.83) 61.58,48.34 56.05,48.34 55.84,48.54 50.51,48.54 49.49,49.56 46.95,49.56 J1.8 ; J6.2 55.46,24.38 53.45,26.39 53.45,31.12 v1(53.05,31.52) 52.92,31.65 U1.22
  BOTTOM w0.203: v1(62.09,47.83) 62.19,47.73 62.19,37.92 57.98,33.71 56.17,33.71 53.99,31.52 v1(53.05,31.52)
AREF: length 65.8
  TOP w0.203: J2.8 25.11,52.1 64.48,52.1 64.78,51.79 64.78,34.49 62.32,32.03 R25.2
EXTAL: length 4.8
  TOP w0.203: U1.5 58.37,35.19 R1.1
LEDRGB_BLUE: length 3.7
  TOP w0.508: D4.3 32.84,43.33 v1(33.87,43.33) TP19.1 R20.1
LEDRGB_GREEN: length 3.6
  TOP w0.508: D4.4 33.1,45.11 v1(33.87,45.11) TP18.1 R19.1
LEDRGB_RED: length 7.3
  TOP w0.508: D4.1 v1(30.65,46.17) 31.37,46.89 TP17.1 R18.2
MMA8451_BYP: length 6.9
  TOP w0.127: U7.2 v2(35.86,39.4)
  TOP w0.203: v1(37.55,41.05) C19.1 TP24.1 35.86,40.24 v2(35.86,39.4)
Net_42: length 2.8
  TOP w0.127: 35.36,33.31 v2(35.36,30.53)
Net_98: length 2.8
  TOP w0.127: 34.09,34.08 v2(31.33,34.08)
Net_99: length 2.8
  TOP w0.127: 35.36,35.86 v2(35.36,38.64)
Net_100: length 2.8
  TOP w0.127: 36.64,35.08 v2(39.39,35.08)
Net_101: length 3.6
  TOP w0.127: 36.64,34.58 v2(40.25,34.58)
Net_102: length 2.8
  TOP w0.127: 36.36,33.31 v2(36.36,30.53)
PTA2/CMP0_OUT/SWD_DIO: length 29
  TOP w0.203: R52.2 v1(57.59,27.33)
  BOTTOM w0.203: v1(57.59,27.33) 61.81,23.11 61.81,5.99 J4.4
PTA5/RTC_CLKIN/TPM0_CH1/SPI0_SS: length 27.8
  TOP w0.203: v1(50.89,47.02) 53.93,43.97 53.93,36.41 U1.7
  BOTTOM w0.203: v1(50.89,47.02) 48.25,49.66 37.71,49.66 J2.3
PTA6/TPM0_CH0/SPI0_MISO: length 32.2
  TOP w0.203: v1(50.13,47.02) 53.42,43.72 53.42,36.4 U1.8
  BOTTOM w0.203: v1(50.13,47.02) 47.87,49.28 33.01,49.28 J2.5
PTA7/IRQ_4/SPI0_MISO/SPI0_MOSI: length 27.8
  TOP w0.203: U1.11 51.92,43.07 48.86,46.13 42.92,46.13 39.39,49.66 35.17,49.66 J2.4
PTB3/IRQ_10/I2C0_SCL/UART0_TX: length 74.8
  TOP w0.203: v1(29.68,47.27) 22.31,47.27 J2.10 ; R48.1 v1(29.68,40.03) ; U1.17 48.87,33.69 v1(48.48,33.3) 48.67,33.11 48.67,32.35 45.81,29.49 R21.2
  BOTTOM w0.203: J2.10 20.41,49.17 29.93,49.17 31.46,47.65 45.43,47.65 47.97,45.11 47.97,41.05 48.48,40.54 48.48,37.49 49.62,36.35 49.62,34.44 v1(48.48,33.3) ; v1(29.68,40.03) v1(29.68,47.27)
PTB4/IRQ_11/I2C0_SDA/UART0_RX: length 68.2
  TOP w0.203: v1(29.17,47.9) 24.22,47.9 J2.9 ; R22.2 47.33,30.38 49.24,32.28 v1(49.24,33.17) 49.26,33.19 U1.18 ; R49.1 v1(29.17,39.01)
  BOTTOM w0.203: v1(49.24,33.17) 50,33.93 50,36.6 48.86,37.74 48.86,40.79 48.35,41.3 48.35,45.36 45.68,48.03 31.71,48.03 30.19,49.56 22.57,49.56 J2.9 ; v1(29.17,39.01) v1(29.17,47.9)
PTB6/IRQ_2/LPTMR0_ALT3/TPM1_CH1: length 41.2
  TOP w0.203: U1.1 54.78,33.19 55.21,32.77 55.21,30.62 v1(55.26,30.57) 55.88,29.95 56.78,29.95 R44.1 ; v1(62.45,32.92) 62.57,32.92 64.38,34.72 64.38,48.29 63.11,49.56 57.11,49.56 J1.4
  BOTTOM w0.203: v1(55.26,30.57) 55.83,30 57.32,30 60.49,33.17 62.19,33.17 v1(62.45,32.92)
PTB7/IRQ_3/TPM1_CH0: length 43.3
  TOP w0.203: U1.2 55.33,33.69 55.59,33.44 55.59,31.01 v1(56.1,30.51) 56.22,30.38 R45.1 ; v1(62.57,33.68) 62.7,33.68 63.97,34.95 63.97,48.03 62.85,49.15 56.76,49.15 56.35,49.56 52.03,49.56 J1.6
  BOTTOM w0.203: v1(56.1,30.51) 57.21,30.51 60.39,33.68 v1(62.57,33.68)
PTB10/TPM0_CH1/SPI0_SS_B: length 29.5
  TOP w0.203: U1.9 52.92,43.46 49.44,46.94 43.98,46.94 v1(43.78,47.14) 43.27,47.14 41.62,48.79 J2.1 ; R18.1 v1(38.57,46)
  BOTTOM w0.203: v1(38.57,46) 39.71,46 40.86,47.14 v1(43.78,47.14)
PTB11/TPM0_CH0/SPI0_MISO: length 29.6
  TOP w0.203: U1.10 52.42,43.28 49.16,46.53 43.24,46.53 v1(43.14,46.63) 43.01,46.63 39.08,50.57 J2.2 ; R19.2 v1(38.57,45.11)
  BOTTOM w0.203: v1(43.14,46.63) 40.98,46.63 39.46,45.11 v1(38.57,45.11)
PTB13/CLKOUT32K/TPM1_CH1/RTC_CL: length 69
  TOP w0.203: J4.5 59.75,3.73 55.38,3.73 54.27,4.85 54.27,12.67 53.56,13.39 53.56,14.22 49.19,18.59 49.19,24.23 50.76,25.81 52.29,25.81 53.05,26.57 53.05,29.51 v1(52.92,29.64) 52.92,30.89 52.42,31.39 U1.21 ; R20.2 38.7,43.33 41.49,40.54 41.49,33.43 40.03,31.97 v1(40.03,30.38)
  BOTTOM w0.203: v1(40.03,30.38) 40.77,29.64 v1(52.92,29.64)
RST_TGTMCU: length 138.7
  TOP w0.203: v1(26.63,15.9) 26.76,15.9 31.33,20.47 v1(31.33,28.73) ; v1(39.23,20.9) 39.23,15.11 41.74,12.6 41.74,10.06 41.36,9.68 R31.2 39.2,9.68 J11.2 ; U1.23 53.42,31.91 53.86,31.47 53.86,26.59 57.11,23.34 J7.10 ; SW1.1 2.76,32.28 5.55,29.49 R13.2 C13.1 v1(7.96,23.39)
  BOTTOM w0.203: J7.10 57.87,19.71 58.38,20.22 58.38,20.98 58,21.36 53.1,21.36 52.54,20.8 39.33,20.8 v1(39.23,20.9) ; v1(7.96,23.39) 8.6,22.76 14.69,22.76 22,30.06 22,33.49 23.33,34.82 25.74,34.82 26.89,33.68 26.89,29.11 27.27,28.73 v1(31.33,28.73) ; v1(26.63,15.9) 26.63,15.77 28.41,14 28.41,12.47 33.11,7.77 J11.2 37.3,6.88 J3.3
SDA_EXTAL: length 7.6
  TOP w0.203: Y2.3 30.96,12.73 28.54,12.73 28.16,13.11 C11.1 27.88,13.77 U2.17
SDA_JTAG_TCLK: length 21.2
  TOP w0.203: J8.4 6.69,8.41 7.71,9.42 21.81,9.42 22.19,9.81 U2.12
SDA_JTAG_TDI: length 19.1
  TOP w0.203: J8.8 9.23,8.15 9.99,8.92 22.06,8.92 22.69,9.55 U2.13
SDA_JTAG_TDO: length 21.8
  TOP w0.203: v1(11.9,8.15) 12.15,8.41 22.31,8.41 23.19,9.28 U2.14
  BOTTOM w0.203: J8.6 7.96,8.28 8.6,8.92 11.14,8.92 v1(11.9,8.15)
SDA_JTAG_TMS: length 27.4
  TOP w0.203: v1(12.66,7.77) 12.79,7.9 22.69,7.9 23.71,8.92 23.71,10.82 24.09,11.2 R15.2 23.69,12.36 U2.15
  BOTTOM w0.203: J8.2 5.42,8.28 6.57,9.42 11.39,9.42 12.66,8.15 v1(12.66,7.77)
SDA_LED: length 3.7
  TOP w0.203: TP6.1 22.19,17.92 U2.29
  TOP w0.508: D1.C v1(22.44,20.6) 22.44,19.96 TP6.1
SDA_LED_R: length 2.5
  TOP w0.203: R10.2 23.33,24.41 v1(23.46,24.28)
  TOP w0.508: D1.A R10.2
SDA_PTD5: length 21.4
  TOP w0.203: U2.30 21.69,18.68 v1(21.55,18.82) ; v1(27.9,5.11) J3.1
  BOTTOM w0.203: v1(27.9,5.11) 27.9,9.8 25.11,12.6 25.11,17.93 24.47,18.57 21.81,18.57 v1(21.55,18.82)
SDA_PTD6: length 2.2
  TOP w0.203: R11.1 20.54,19.08 21.19,18.42 U2.31
SDA_RST: length 30.2
  TOP w0.203: v1(26.63,14.88) 26.52,14.77 U2.19 ; TP5.1 R9.1 R8.2 ; TP5.1 28.16,12.47 v1(27.39,13.23) ; TP5.1 27.52,10.57 27.52,9.17 24.47,6.12 11.01,6.12 J8.10
  BOTTOM w0.203: v1(27.39,13.23) 27.39,14.12 v1(26.63,14.88)
SDA_RST_TGTMCU: length 20.4
  TOP w0.203: R31.1 38.19,11.2 J11.1 ; U2.21 25.36,15.77 26.57,16.98 v1(27.01,16.98)
  BOTTOM w0.203: v1(27.01,16.98) 27.2,16.98 29.43,14.76 29.43,13.23 32.35,10.31 J11.1
SDA_SPI0_SCK: length 8.1
  TOP w0.203: U2.26 23.69,18.55 24.22,19.08 v1(24.22,20.6) 24.22,21.87 25.09,22.74 U4.12
SDA_SPI0_SIN: length 10.1
  TOP w0.203: U2.28 22.69,19.2 23.71,20.22 23.71,22.12 v1(24.98,23.39) 26.93,25.34 U4.8
SDA_SPI0_SOUT: length 14.8
  TOP w0.203: v1(23.46,19.27) 23.19,19 U2.27 ; U4.2 v1(33.62,22.09)
  BOTTOM w0.203: v1(23.46,19.27) 24.85,19.27 25.11,19.52 25.11,20.85 26,21.74 33.27,21.74 v1(33.62,22.09)
SDA_SWD_EN: length 19.6
  TOP w0.203: U4.10 28.9,24.04 29.17,23.77 29.17,22.38 28.89,22.09 U4.13 26.73,22.09 26.38,21.74 v1(26.38,21.23) ; U2.16 24.19,12.73 24.32,12.6 v1(26,12.6) 26.5,12.09 R4.2
  BOTTOM w0.203: v1(26,12.6) 25.49,13.11 25.49,20.47 26.25,21.23 v1(26.38,21.23)
SDA_SWD_OE_B: length 15.2
  TOP w0.203: U2.20 26.25,15.27 26.38,15.39 27.01,15.39 v1(28.41,16.79) 30.31,18.69 R7.1 35.39,21.23 35.19,21.44 U4.1
SDA_USB_CONN_DN: length 10.8
  TOP w0.203: v1(15.33,15.77) R5.1 ; D6.2 12.09,17.24 12.79,16.54 v1(12.79,16.28) 12.41,15.9 11.52,15.9 10.56,16.86 8.94,16.86 8.72,17.08 J9.2
  BOTTOM w0.203: v1(12.79,16.28) 13.3,15.77 v1(15.33,15.77)
SDA_USB_CONN_DP: length 11.2
  TOP w0.203: J9.3 8.72,16.28 8.94,16.5 10.41,16.5 11.37,15.54 12.81,15.54 v1(13.55,16.28) 13.55,16.79 14,17.24 D6.3 ; R6.1 v1(15.33,16.92)
  BOTTOM w0.203: v1(15.33,16.92) 15.33,16.54 14.92,16.13 13.7,16.13 v1(13.55,16.28)
SDA_USB_DN: length 3
  TOP w0.203: U2.4 19.39,15.77 19.31,15.84 17.18,15.84 R5.2
SDA_USB_DP: length 3.3
  TOP w0.203: R6.2 17.83,16.2 19.31,16.2 19.39,16.27 U2.3
SDA_USB_P5V_SENSE: length 5.8
  TOP w0.203: R12.2 R14.1 v1(18.88,20.47) 18.88,19.96 TP7.1 20.69,18.16 U2.32
SDA_USB_VOUT33: length 5.5
  TOP w0.203: U2.5 17.62,15.27 17.53,15.18 16.51,15.18 C12.1 v1(14.82,14.5)
SDA_USBSHIELD: length 14.2
  TOP w0.508: 7.44,10.64 J9.S2 ; J9.S2 6.4,11.83 ; J9.S2 8.49,11.83 ; J9.S4 1.99,13.03 ; J9.S4 3.04,11.83 ; J9.S4 1.99,10.64 ; 10.88,10.78 L4.1 9.94,11.62 ; J9.S3 1.99,21.93 ; J9.S3 1.99,19.54 ; J9.S3 3.04,20.73 ; 6.4,20.73 J9.S1 7.44,21.93
  vias: v1(4.03,11.71)
SDA_XTAL: length 12.9
  TOP w0.203: Y2.1 35.44,16.62 35.14,16.92 30.19,16.92 28.16,14.88 C10.1 27.79,14.27 U2.18
SW_LLWU: length 23.2
  TOP w0.203: v1(55.28,13.61) R54.2 C33.1 SW2.1 ; R37.2 47.97,26.44 47.97,17.88 v1(52.24,13.61)
  BOTTOM w0.203: v1(55.28,13.61) v1(52.24,13.61)
SW_NMI_B: length 27.9
  TOP w0.203: v1(53.35,8.53) 53.35,12.37 52.74,12.98 52.74,13.82 48.4,18.16 48.4,24.71 50.38,26.7 R36.2 ; SW3.1 C34.1 R55.2 v1(55.31,8.53)
  BOTTOM w0.203: v1(55.31,8.53) v1(53.35,8.53)
SWD_CLK_TGTMCU: length 35
  TOP w0.203: J6.1 53.3,22.76 J7.4 ; v1(26.5,24.03) 26.5,23.77 26.89,23.39 U4.11
  BOTTOM w0.203: J6.1 52.92,21.89 52.34,21.31 39.64,21.31 39.43,21.51 38.42,21.51 37.43,22.5 35.78,22.5 34.51,23.77 30.7,23.77 29.68,24.79 27.27,24.79 v1(26.5,24.03)
SWD_DIO_TGTMCU: length 42.1
  TOP w0.203: R33.2 54.83,26.24 57.75,23.32 v1(57.75,20.85) ; U4.3 33.63,22.74 v1(33.11,23.27) ; v1(29.55,24.16) 29.01,24.69 U4.9
  BOTTOM w0.203: v1(57.75,20.85) 53.17,20.85 J7.2 51.35,20.4 38.77,20.4 37.05,22.12 35.52,22.12 34.38,23.27 v1(33.11,23.27) 30.44,23.27 v1(29.55,24.16)
TC_74125_SPARE_I_TP: length 2.4
  TOP w0.203: TP11.1 36.27,24.04 U4.5
TC_74125_SPARE_O_TP: length 2.3
  TOP w0.203: TP13.1 36.44,24.69 U4.6
TC_EXTAL_TP: length 3
  TOP w0.203: U2.10 21.19,12.62 19.9,11.33 TP3.1
TC_SDA_USB_ID_TP: length 6.3
  TOP w0.203: TP2.1 12.79,14.12 12.15,14.76 11.39,14.76 10.67,15.48 J9.4
TC_VBAT_TP: length 2
  TOP w0.203: TP1.1 21.69,11.85 U2.11
TC_XTAL_TP: length 4.7
  TOP w0.203: TP4.1 17.87,11.33 18.63,12.09 19.9,12.09 20.69,12.88 U2.9
THER_A: length 2.5
  TOP w0.203: R34.2 R41.1 C32.1
THER_B: length 4.6
  TOP w0.203: C31.1 R40.1 44.67,35.46 R35.2
THER_N: length 4.2
  TOP w0.203: R40.2 C30.2 44.41,39.9 RT1.2 R39.1
THER_P: length 4.2
  TOP w0.203: R41.2 C30.1 45.94,39.9 RT1.1 R38.2
TOUCH_A: length 9.1
  TOP w0.203: R45.2 v1(60.46,30.38) R29.2
  BOTTOM w0.203: v1(67.65,30.38) v1(60.46,30.38)
TOUCH_B: length 12.3
  TOP w0.203: R30.2 v1(60.54,28.73) R44.2
  BOTTOM w0.203: v1(60.54,28.73) v1(70.95,28.73)
UART0_RX_TGTMCU: length 28.9
  TOP w0.203: v1(26.25,18.31) 24.37,18.31 24.19,18.13 U2.25 ; R17.1 44.28,25.55 42.2,23.47 42.2,17.88 v1(42.13,17.81)
  BOTTOM w0.203: v1(42.13,17.81) 41.74,18.19 26.38,18.19 v1(26.25,18.31)
UART0_TX_TGTMCU: length 43
  TOP w0.203: v1(48.09,32.6) 45.75,32.6 42.38,29.24 42.38,26.29 41.11,25.02 v1(41.11,18.97) ; v1(27.01,18.82) 27.01,18.31 25.97,17.27 U2.24 ; R16.1 v1(50.51,37.62)
  BOTTOM w0.203: v1(27.01,18.82) 27.14,18.69 40.83,18.69 v1(41.11,18.97) ; v1(48.09,32.6) 49.43,32.6 50.38,33.55 50.38,37.49 v1(50.51,37.62)
VREF_CAP/CMP_IN5/PTB2/IRQ_7/UAR: length 35.8
  TOP w0.203: v1(47.52,31.97) 44.41,28.85 R17.2 ; U1.14 50.01,35.19 v1(49.11,36.09) C35.1 49.11,41.05 v1(50.13,42.06)
  BOTTOM w0.203: v1(47.52,31.97) 47.52,33.11 49.11,34.7 v1(49.11,36.09) ; J1.1 61.81,49.17 55.33,49.17 50.13,43.97 v1(50.13,42.06)
XTAL: length 3
  TOP w0.203: R3.1 57.22,35.69 U1.6
N20057318: length 7.2
  TOP w0.762: U6.3 15.46,31.46 v1(15.46,29.81) C15.1 17.21,28.85 D2.C D7.C
N20181399: length 8.5
  TOP w0.127: U7.7 31.06,34.58 v1(30.7,34.95)
  TOP w0.203: v1(30.7,34.95) R23.2 R24.1 TP25.1
N51885583: length 6.8
  TOP w0.203: Y1.1 59.14,40.63 R2.1 59.91,39.01 60.54,38.38 C2.1 R1.2
N51886520: length 5.7
  TOP w0.203: R52.1 R33.1 54.83,29.49 v1(54.57,29.74) 54.27,30.05 54.27,31.67 53.92,32.02 U1.24
N51910298: length 6.9
  TOP w0.203: Y1.4 57.62,40.63 R2.2 56.73,39.01 56.1,38.38 C7.1 R3.2

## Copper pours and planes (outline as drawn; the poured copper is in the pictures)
GND on TOP: 7.07,13.11 11.65,13.11 11.65,14.63 11.26,15.01 7.07,15.01
GND on BOTTOM: 66.64,45.16 66.64,6.87 78.93,6.87 78.93,45.16
P3V3_VREG on TOP: 10.38,36.73 10.38,43.97 18.12,43.97 18.12,36.73
P5V0_SDA_USB_CONN_VBUS on TOP: 7.07,18.95 7.07,17.61 10.31,17.61 10.88,18.19 10.88,19.96 11.65,20.73 12.79,20.73 12.79,22.38 12.53,22.63 9.49,22.63 8.98,22.12 8.98,19.71 8.6,19.33 7.45,19.33
(no net) on TOP: 12.73,1.27 8.53,2.07 4.92,4.34 10.25,9.68 12.28,9.68 12.28,16.54 15.33,16.54 15.33,23.27 1.27,23.27 1.27,40.64 4.62,48.72 12.7,52.07 68.58,52.07 74.64,50.33 78.86,45.63 66.4,45.63 66.26,45.49 66.26,6.25 78.01,6.25 73.91,2.59 68.58,1.27 ; 47 cut-outs
SDA_USBSHIELD on TOP: 1.87,9.93 11.39,9.93 11.65,10.19 11.65,12.09 3.64,12.09 3.64,20.22 7.84,20.22 7.84,22.12 7.58,22.38 1.74,22.38 1.49,22.12 1.49,10.31

Small or netless copper shapes (teardrops, artwork), in the pictures only: 1 on BOTTOM

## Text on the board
BOTTOM: 170-28172 REV B | 2 OF 8 | SECONDARY SIDE
Board Geometry/Soldermask Bottom: 6 OF 8 | SECONDARY SOLDERMASK
Ref Des/Silkscreen Bottom: J3 | J2 | J4 | J1 | SCH | 700 | B3 | B4 | SDA_PTD5 | AREF | IOREF | GND | Reset | B0 | 3.3V | A6 | 5V | A7 | A5 | B11 | VIN | B10 | [PT] | A9 | A0 | A8 | B5 | A12 | B7 | A2 | NC | B13 | B6 | SDA_PTD6 | B1 | B2 | 8 OF 8 | SECONDARY SILKSCREEN
User.Comments: 1 OF 1 | TEST PROBE | 1/1 | 1
TOP: 1 OF 8 | PRIMARY SIDE
Board Geometry/Soldermask Top: 3 OF 8 | PRIMARY SOLDERMASK
Ref Des/Silkscreen Top: OPENSDA | RST | JTAG | SDA | ACCEL | GND | SWD | LLWU | NMI | 5 OF 8 | PRIMARY SILKSCREEN | FRDM- KL03Z
DIMENSION: GRID ORIGIN | PRIMARY DATUM
BODY_CENTER: 22. INTENTIONAL SHORT IN J6 BETWEEN NETS ADC0_SE12/CMP0_IN2/PTA0/IRQ_0/L AND SWD_CLK_TGTMCU. | 6 INTENTIONAL DANGLING VIAS IN U7 AREA. | 16 | 17 | 8
PASTEMASK_TOP: 4 OF 8 | PASTEMASK TOP
User.5: 7 OF 8 | SECONDARY PASTEMASK
User.13: 02-26-14 | H.X. | B | ORIGINAL RELEASE | RESPIN PER ECO49251
User.17: FIGURE | SIZE | 10.0 | 12.0 | 18.0 | 20.0 | 28.0 | 40.0 | 41.0 | 73.0 | 125.0 | DRILL CHART: TOP to BOTTOM | ALL UNITS ARE IN MILS | TOLERANCE | +0.0/-10.0 | +2.0/-2.0 | +0.0/-6.0 | +3.0/-3.0 | PLATED | NON-PLATED | QTY | 490 | 14 | 6 | 13 | 20 | 38 | 2 | 4
